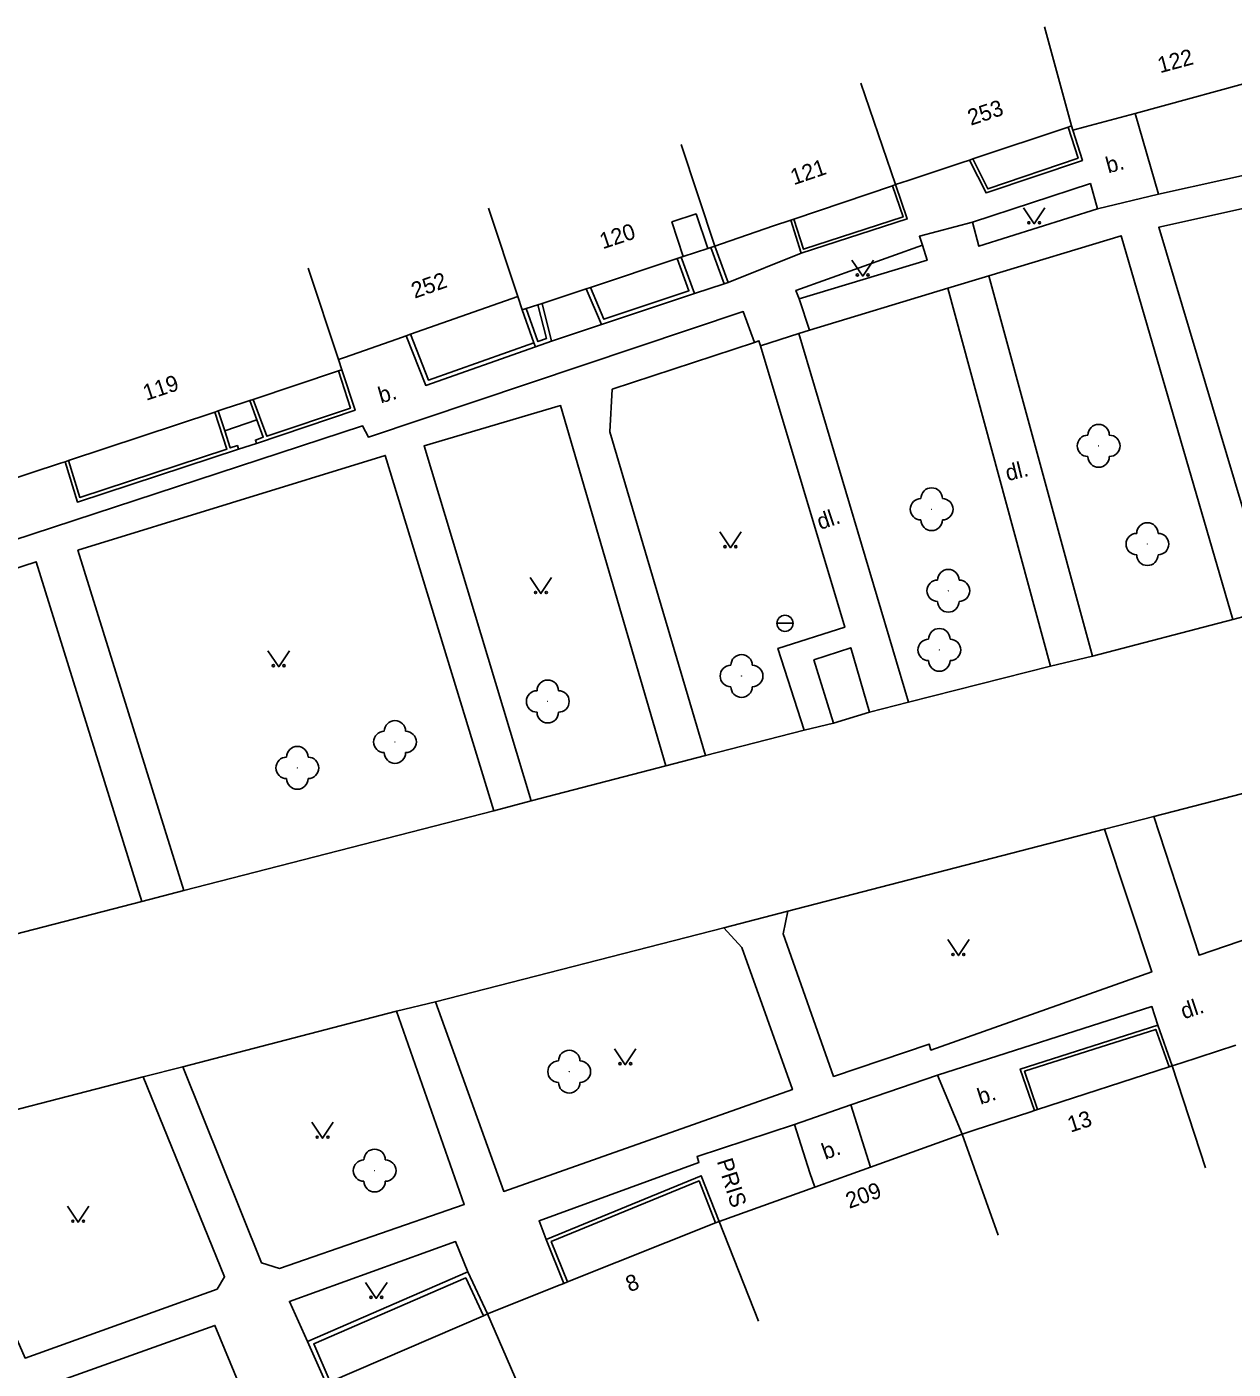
# Model space of a CAD drawing. Extents: x -577457 to -568404, y -1208466 to -1201387.
# Drawn here: x -574973.4 to -574917, y -1204035.2 to -1203972.5 of the extents above; entities that cross this region are included whole.
import ezdxf

# ---------------------------------------------------------------- set-up
doc = ezdxf.new("R2010")
doc.units = 0
for name, color, linetype in [('BUDOVY_MĚŘ', 7, 'Continuous'), ('POMOC_POPIS', 7, 'Continuous'), ('ROZHRANÍ_PLOCH', 7, 'Continuous'), ('ZELEŇ', 7, 'Continuous'), ('ZN_DOPLŇKOVÉ', 7, 'Continuous'), ('ZN_KULTUR', 7, 'Continuous'), ('Č_POPIS_ORIENT', 7, 'Continuous')]:
    doc.layers.add(name, color=color, linetype=linetype)

msp = doc.modelspace()

# ---------------------------------------------------------------- linework, layer by layer
at = {"layer": 'BUDOVY_MĚŘ'}
for points in [[(-574924.57, -1203977.14), (-574925.83, -1203972.51)], [(-574915.23, -1203974.82), (-574921.6, -1203976.55)], [(-574934.41, -1203975.14), (-574932.8, -1203979.88)], [(-574924.73, -1203977.19), (-574929.18, -1203978.68)], [(-574924.57, -1203977.14), (-574924.73, -1203977.19)], [(-574924.52, -1203977.34), (-574924.57, -1203977.14)], [(-574923.94, -1203977.18), (-574924.52, -1203977.34)], [(-574942.81, -1203978), (-574941.24, -1203982.75)], [(-574929.34, -1203978.73), (-574929.69, -1203978.85)], [(-574929.18, -1203978.68), (-574929.34, -1203978.73)], [(-574937.55, -1203981.49), (-574932.94, -1203979.93)], [(-574932.94, -1203979.93), (-574932.8, -1203979.88)], [(-574932.21, -1203979.68), (-574932.8, -1203979.88)], [(-574951.81, -1203980.98), (-574950.44, -1203985.11)], [(-574938.49, -1203981.81), (-574937.69, -1203981.54)], [(-574937.69, -1203981.54), (-574937.55, -1203981.49)], [(-574942.71, -1203983.24), (-574941.57, -1203982.86)], [(-574941.57, -1203982.86), (-574941.43, -1203982.81)], [(-574941.43, -1203982.81), (-574941.24, -1203982.75)], [(-574941.24, -1203982.75), (-574940.93, -1203982.64)], [(-574958.82, -1203988.05), (-574960.23, -1203983.78)], [(-574947.05, -1203984.68), (-574943, -1203983.33)], [(-574943, -1203983.33), (-574942.81, -1203983.27)], [(-574942.81, -1203983.27), (-574942.71, -1203983.24)], [(-574947.24, -1203984.74), (-574947.05, -1203984.68)], [(-574950.44, -1203985.11), (-574955.46, -1203986.87)], [(-574950.44, -1203985.11), (-574950.24, -1203985.73)], [(-574950.24, -1203985.73), (-574950.05, -1203985.67)], [(-574950.05, -1203985.67), (-574949.5, -1203985.49)], [(-574949.5, -1203985.49), (-574949.31, -1203985.43)], [(-574955.65, -1203986.94), (-574956.09, -1203987.09)], [(-574955.46, -1203986.87), (-574955.65, -1203986.94)], [(-574958.53, -1203987.95), (-574958.82, -1203988.05)], [(-574958.66, -1203988.53), (-574958.82, -1203988.05)], [(-574962.8, -1203989.91), (-574958.82, -1203988.58)], [(-574958.82, -1203988.58), (-574958.66, -1203988.53)], [(-574963.29, -1203990.07), (-574962.96, -1203989.96)], [(-574962.96, -1203989.96), (-574962.8, -1203989.91)], [(-574971.43, -1203992.77), (-574964.6, -1203990.5)], [(-574964.6, -1203990.5), (-574964.44, -1203990.45)], [(-574964.44, -1203990.45), (-574964.15, -1203990.35)], [(-574971.8, -1203992.89), (-574971.59, -1203992.82)], [(-574971.59, -1203992.82), (-574971.43, -1203992.77)], [(-574926.16, -1204023.08), (-574920.02, -1204021.09)], [(-574920.02, -1204021.09), (-574919.87, -1204021.04)], [(-574919.87, -1204021.04), (-574919.47, -1204020.91)], [(-574918.32, -1204025.8), (-574919.87, -1204021.04)], [(-574926.53, -1204023.2), (-574926.31, -1204023.13)], [(-574926.31, -1204023.13), (-574926.16, -1204023.08)], [(-574929.69, -1204024.23), (-574933.97, -1204025.77)], [(-574929.69, -1204024.23), (-574929.07, -1204024.03)], [(-574928, -1204028.94), (-574929.69, -1204024.23)], [(-574936.57, -1204026.7), (-574941.04, -1204028.31)], [(-574941.2, -1204028.37), (-574941.04, -1204028.31)], [(-574939.19, -1204032.96), (-574941.04, -1204028.31)], [(-574948.12, -1204031.13), (-574941.2, -1204028.37)], [(-574948.59, -1204031.32), (-574948.29, -1204031.2)], [(-574948.29, -1204031.2), (-574948.12, -1204031.13)], [(-574959.2, -1204035.79), (-574952.05, -1204032.71)], [(-574952.05, -1204032.71), (-574951.85, -1204032.62)], [(-574951.85, -1204032.62), (-574951.19, -1204032.36)], [(-574949.86, -1204037.21), (-574951.85, -1204032.62)]]:
    msp.add_lwpolyline(points, dxfattribs=at)
at = {"layer": 'ROZHRANÍ_PLOCH'}
for points in [[(-574921.6, -1203976.55), (-574920.52, -1203980.33)], [(-574920.52, -1203980.33), (-574914.31, -1203978.95)], [(-574929.2, -1203981.64), (-574923.69, -1203979.83), (-574923.36, -1203981.01)], [(-574923.36, -1203981.01), (-574920.52, -1203980.33)], [(-574915.17, -1203999.69), (-574920.5, -1203981.87), (-574912.77, -1203980.16), (-574908.46, -1203998.01)], [(-574923.36, -1203981.01), (-574928.91, -1203982.76), (-574929.2, -1203981.64)], [(-574931.53, -1203982.71), (-574931.68, -1203982.29), (-574929.2, -1203981.64)], [(-574928.44, -1203984.14), (-574922.25, -1203982.27), (-574917.04, -1204000.19)], [(-574940.61, -1203984.45), (-574937.2, -1203983.08)], [(-574937.3, -1203985.22), (-574937.45, -1203984.82), (-574931.53, -1203982.71)], [(-574931.53, -1203982.71), (-574931.32, -1203983.41), (-574937.3, -1203985.22)], [(-574930.36, -1203984.72), (-574928.44, -1203984.14)], [(-574928.44, -1203984.14), (-574923.6, -1204001.9)], [(-574936.82, -1203986.68), (-574930.36, -1203984.72)], [(-574925.55, -1204002.37), (-574930.36, -1203984.72)], [(-574936.82, -1203986.68), (-574937.3, -1203985.22)], [(-574995.99, -1204004.75), (-574996.24, -1204003.87), (-574973.96, -1203996.86), (-574974.07, -1203996.52), (-574957.69, -1203991.15), (-574957.42, -1203991.67), (-574939.91, -1203985.81), (-574939.38, -1203987.25)], [(-574948.86, -1203987.19), (-574946.53, -1203986.42)], [(-574939.11, -1203987.41), (-574937.31, -1203986.84)], [(-574937.31, -1203986.84), (-574936.82, -1203986.68)], [(-574932.19, -1204004.05), (-574937.31, -1203986.84)], [(-574941.67, -1204006.55), (-574946.14, -1203991.43), (-574946.03, -1203989.44), (-574939.38, -1203987.25)], [(-574939.11, -1203987.41), (-574939.18, -1203987.17), (-574939.38, -1203987.25)], [(-574937.06, -1204005.36), (-574938.29, -1204001.54), (-574935.17, -1204000.55), (-574939.11, -1203987.41)], [(-574949.81, -1204008.66), (-574954.82, -1203992.08), (-574948.44, -1203990.2), (-574943.53, -1204007.02)], [(-574964.13, -1203991.38), (-574962.63, -1203990.87)], [(-574963.49, -1203992.24), (-574962.65, -1203991.97)], [(-574966.04, -1204012.85), (-574970.99, -1203996.96), (-574956.63, -1203992.53), (-574951.56, -1204009.13)], [(-574982.66, -1204017.14), (-574987.79, -1204002.33), (-574972.94, -1203997.49), (-574968, -1204013.37)], [(-574917.04, -1204000.19), (-574915.17, -1203999.69)], [(-574923.6, -1204001.9), (-574917.04, -1204000.19)], [(-574935.7, -1204005.03), (-574936.61, -1204002.08), (-574934.89, -1204001.51), (-574934.01, -1204004.52)], [(-574925.55, -1204002.37), (-574923.6, -1204001.9)], [(-574932.19, -1204004.05), (-574925.55, -1204002.37)], [(-574935.7, -1204005.03), (-574934.01, -1204004.52)], [(-574934.01, -1204004.52), (-574932.19, -1204004.05)], [(-574937.06, -1204005.36), (-574935.7, -1204005.03)], [(-574941.67, -1204006.55), (-574937.06, -1204005.36)], [(-574949.81, -1204008.66), (-574943.53, -1204007.02)], [(-574943.53, -1204007.02), (-574941.67, -1204006.55)], [(-574920.73, -1204009.4), (-574918.62, -1204015.87), (-574911.78, -1204013.53), (-574913.34, -1204008.46), (-574914.29, -1204007.73)], [(-574920.73, -1204009.4), (-574914.29, -1204007.73)], [(-574951.56, -1204009.13), (-574949.81, -1204008.66)], [(-574966.04, -1204012.85), (-574951.56, -1204009.13)], [(-574923.03, -1204009.98), (-574920.73, -1204009.4)], [(-574937.82, -1204013.82), (-574938.04, -1204014.88), (-574935.69, -1204021.53), (-574931.23, -1204020.02), (-574931.14, -1204020.3), (-574920.83, -1204016.65), (-574923.03, -1204009.98)], [(-574937.82, -1204013.82), (-574923.03, -1204009.98)], [(-574968, -1204013.37), (-574966.04, -1204012.85)], [(-574982.66, -1204017.14), (-574968, -1204013.37)], [(-574940.82, -1204014.6), (-574937.82, -1204013.82)], [(-574954.29, -1204018.05), (-574951.1, -1204026.9), (-574937.61, -1204022.15), (-574939.98, -1204015.51), (-574940.82, -1204014.6)], [(-574954.29, -1204018.05), (-574940.82, -1204014.6)], [(-574956.11, -1204018.49), (-574954.29, -1204018.05)], [(-574930.84, -1204021.47), (-574920.82, -1204018.27), (-574920.54, -1204019.14)], [(-574966.09, -1204021.08), (-574956.11, -1204018.49)], [(-574966.09, -1204021.08), (-574962.41, -1204030.24), (-574961.58, -1204030.5), (-574952.94, -1204027.52), (-574956.11, -1204018.49)], [(-574967.94, -1204021.55), (-574966.09, -1204021.08)], [(-574978.06, -1204024.16), (-574967.94, -1204021.55)], [(-574978.06, -1204024.16), (-574973.46, -1204034.69), (-574964.49, -1204031.47), (-574964.14, -1204030.9), (-574967.94, -1204021.55)], [(-574934.89, -1204022.86), (-574930.84, -1204021.47)], [(-574930.84, -1204021.47), (-574929.69, -1204024.23)], [(-574937.51, -1204023.78), (-574934.89, -1204022.86)], [(-574933.97, -1204025.77), (-574934.89, -1204022.86)], [(-574949.11, -1204029.15), (-574949.45, -1204028.28), (-574941.98, -1204025.55), (-574942.07, -1204025.27), (-574937.51, -1204023.78)], [(-574937.51, -1204023.78), (-574936.8, -1204026.03), (-574936.57, -1204026.7)], [(-574960.26, -1204033.91), (-574961.11, -1204032.04), (-574953.35, -1204029.25), (-574952.77, -1204030.66)], [(-574970.41, -1204041.38), (-574972.83, -1204036.11), (-574964.59, -1204033.16), (-574963.43, -1204035.98)]]:
    msp.add_lwpolyline(points, dxfattribs=at)
at = {"layer": 'ZELEŇ'}
for centre in [(-574923.31, -1203992.08), (-574931.11, -1203995.04), (-574921.03, -1203996.67), (-574930.33, -1203998.85), (-574930.75, -1204001.61), (-574939.99, -1204002.83), (-574949.04, -1204004.02), (-574956.18, -1204005.91), (-574960.74, -1204007.12), (-574948.04, -1204021.31), (-574957.13, -1204025.93)]:
    msp.add_circle(centre, 0.0005, dxfattribs=at)
for centre, start, end in [((-574923.31, -1203991.58), 0, 179.99999), ((-574923.81, -1203992.08), 89.99999, 269.99999), ((-574922.81, -1203992.08), 270, 89.99999), ((-574923.31, -1203992.58), 179.99999, 359.99999), ((-574931.11, -1203994.54), 0, 179.99999), ((-574931.61, -1203995.04), 89.99999, 269.99999), ((-574930.61, -1203995.04), 270, 89.99999), ((-574931.11, -1203995.54), 179.99999, 359.99999), ((-574921.03, -1203996.17), 0, 179.99999), ((-574921.53, -1203996.67), 89.99999, 269.99999), ((-574920.53, -1203996.67), 270, 89.99999), ((-574921.03, -1203997.17), 179.99999, 359.99999), ((-574930.33, -1203998.35), 0, 179.99999), ((-574930.83, -1203998.85), 89.99999, 269.99999), ((-574929.83, -1203998.85), 270, 89.99999), ((-574930.33, -1203999.35), 179.99999, 359.99999), ((-574930.75, -1204001.11), 0, 179.99999), ((-574931.25, -1204001.61), 89.99999, 269.99999), ((-574930.25, -1204001.61), 270, 89.99999), ((-574939.99, -1204002.33), 0, 179.99999), ((-574940.49, -1204002.83), 89.99999, 269.99999), ((-574939.49, -1204002.83), 270, 89.99999), ((-574930.75, -1204002.11), 179.99999, 359.99999), ((-574949.04, -1204003.52), 0, 179.99999), ((-574949.54, -1204004.02), 89.99999, 269.99999), ((-574948.54, -1204004.02), 270, 89.99999), ((-574939.99, -1204003.33), 179.99999, 359.99999), ((-574949.04, -1204004.52), 179.99999, 359.99999), ((-574956.18, -1204005.41), 0, 179.99999), ((-574956.68, -1204005.91), 89.99999, 269.99999), ((-574955.68, -1204005.91), 270, 89.99999), ((-574960.74, -1204006.62), 0, 179.99999), ((-574956.18, -1204006.41), 179.99999, 359.99999), ((-574961.24, -1204007.12), 89.99999, 269.99999), ((-574960.24, -1204007.12), 270, 89.99999), ((-574960.74, -1204007.62), 179.99999, 359.99999), ((-574948.54, -1204021.31), 89.99999, 269.99999), ((-574948.04, -1204020.81), 0, 179.99999), ((-574947.54, -1204021.31), 270, 89.99999), ((-574948.04, -1204021.81), 179.99999, 359.99999), ((-574957.13, -1204025.43), 0, 179.99999), ((-574957.63, -1204025.93), 89.99999, 269.99999), ((-574956.63, -1204025.93), 270, 89.99999), ((-574957.13, -1204026.43), 179.99999, 359.99999)]:
    msp.add_arc(centre, 0.5, start, end, dxfattribs=at)
at = {"layer": 'ZN_DOPLŇKOVÉ'}
msp.add_line((-574938.335, -1204000.37), (-574937.585, -1204000.37), dxfattribs=at)
for points in [[(-574921.6, -1203976.55), (-574923.94, -1203977.18)], [(-574924.52, -1203977.34), (-574924.07, -1203978.75), (-574928.57, -1203980.27), (-574929.34, -1203978.73)], [(-574924.73, -1203977.19), (-574924.27, -1203978.64), (-574928.49, -1203980.08), (-574929.18, -1203978.68)], [(-574929.69, -1203978.85), (-574932.21, -1203979.68)], [(-574932.94, -1203979.93), (-574932.44, -1203981.39), (-574937.1, -1203982.9), (-574937.55, -1203981.49)], [(-574932.8, -1203979.88), (-574932.25, -1203981.48), (-574937.2, -1203983.08)], [(-574941.57, -1203982.86), (-574942.11, -1203981.25), (-574943.24, -1203981.62), (-574942.71, -1203983.24)], [(-574940.93, -1203982.64), (-574938.49, -1203981.81)], [(-574937.2, -1203983.08), (-574937.69, -1203981.54)], [(-574941.43, -1203982.81), (-574940.8, -1203984.52)], [(-574941.24, -1203982.75), (-574940.61, -1203984.45)], [(-574943, -1203983.33), (-574942.45, -1203984.84), (-574946.42, -1203986.17), (-574947.05, -1203984.68)], [(-574942.81, -1203983.27), (-574942.19, -1203984.97)], [(-574940.61, -1203984.45), (-574940.8, -1203984.52)], [(-574949.31, -1203985.43), (-574947.24, -1203984.74)], [(-574946.53, -1203986.42), (-574947.24, -1203984.74)], [(-574942.19, -1203984.97), (-574946.53, -1203986.42)], [(-574940.8, -1203984.52), (-574942.19, -1203984.97)], [(-574949.5, -1203985.49), (-574949.1, -1203987.06), (-574949.5, -1203987.21), (-574950.05, -1203985.67)], [(-574949.31, -1203985.43), (-574948.86, -1203987.19)], [(-574949.69, -1203987.27), (-574950.24, -1203985.73)], [(-574949.62, -1203987.46), (-574954.74, -1203989.26), (-574955.65, -1203986.94)], [(-574949.69, -1203987.27), (-574954.62, -1203989.01), (-574955.46, -1203986.87)], [(-574956.09, -1203987.09), (-574958.53, -1203987.95)], [(-574949.62, -1203987.46), (-574949.69, -1203987.27)], [(-574948.86, -1203987.19), (-574949.62, -1203987.46)], [(-574962.8, -1203989.91), (-574962.17, -1203991.63), (-574958.26, -1203990.32), (-574958.82, -1203988.58)], [(-574962.65, -1203991.97), (-574958.04, -1203990.42), (-574958.66, -1203988.53)], [(-574964.15, -1203990.35), (-574963.29, -1203990.07)], [(-574962.96, -1203989.96), (-574962.63, -1203990.87)], [(-574971.43, -1203992.77), (-574970.9, -1203994.49), (-574964.03, -1203992.24), (-574964.6, -1203990.5)], [(-574964.13, -1203991.38), (-574964.44, -1203990.45)], [(-574962.63, -1203990.87), (-574962.33, -1203991.68), (-574962.7, -1203991.81), (-574962.65, -1203991.97)], [(-574963.49, -1203992.24), (-574963.54, -1203992.07), (-574963.87, -1203992.18), (-574964.13, -1203991.38)], [(-574971.59, -1203992.82), (-574971.01, -1203994.71), (-574963.49, -1203992.24)], [(-574974.59, -1203993.81), (-574971.8, -1203992.89)], [(-574926.31, -1204023.13), (-574926.97, -1204021.19), (-574920.54, -1204019.14)], [(-574926.16, -1204023.08), (-574926.77, -1204021.29), (-574920.64, -1204019.34), (-574920.02, -1204021.09)], [(-574920.54, -1204019.14), (-574919.87, -1204021.04)], [(-574919.47, -1204020.91), (-574916.9, -1204020.08)], [(-574929.07, -1204024.03), (-574926.53, -1204023.2)], [(-574933.97, -1204025.77), (-574936.57, -1204026.7)], [(-574949.11, -1204029.15), (-574941.87, -1204026.17), (-574941.04, -1204028.31)], [(-574948.12, -1204031.13), (-574948.88, -1204029.25), (-574941.97, -1204026.41), (-574941.2, -1204028.37)], [(-574948.29, -1204031.2), (-574949.11, -1204029.15)], [(-574960.26, -1204033.91), (-574952.77, -1204030.66)], [(-574952.77, -1204030.66), (-574951.85, -1204032.62)], [(-574959.2, -1204035.79), (-574959.97, -1204034.02), (-574952.87, -1204030.94), (-574952.05, -1204032.71)], [(-574951.19, -1204032.36), (-574948.59, -1204031.32)], [(-574959.4, -1204035.88), (-574960.26, -1204033.91)]]:
    msp.add_lwpolyline(points, dxfattribs=at)
msp.add_circle((-574937.96, -1204000.37), 0.375, dxfattribs=at)
at = {"layer": 'ZN_KULTUR'}
for points in [[(-574926.82, -1203980.96), (-574926.32, -1203981.71), (-574925.82, -1203980.96)], [(-574934.83, -1203983.4), (-574934.33, -1203984.15), (-574933.83, -1203983.4)], [(-574941.01, -1203996.09), (-574940.51, -1203996.84), (-574940.01, -1203996.09)], [(-574949.86, -1203998.23), (-574949.36, -1203998.98), (-574948.86, -1203998.23)], [(-574962.11, -1204001.65), (-574961.61, -1204002.4), (-574961.11, -1204001.65)], [(-574930.36, -1204015.14), (-574929.86, -1204015.89), (-574929.36, -1204015.14)], [(-574945.92, -1204020.24), (-574945.42, -1204020.99), (-574944.92, -1204020.24)], [(-574960.06, -1204023.67), (-574959.56, -1204024.42), (-574959.06, -1204023.67)], [(-574971.48, -1204027.59), (-574970.98, -1204028.34), (-574970.48, -1204027.59)], [(-574957.55, -1204031.15), (-574957.05, -1204031.9), (-574956.55, -1204031.15)]]:
    msp.add_lwpolyline(points, dxfattribs=at)
for centre in [(-574926.57, -1203981.66), (-574926.07, -1203981.66), (-574934.58, -1203984.1), (-574934.08, -1203984.1), (-574940.76, -1203996.79), (-574940.26, -1203996.79), (-574949.61, -1203998.93), (-574949.11, -1203998.93), (-574961.86, -1204002.35), (-574961.36, -1204002.35), (-574930.11, -1204015.84), (-574929.61, -1204015.84), (-574945.67, -1204020.94), (-574945.17, -1204020.94), (-574959.81, -1204024.37), (-574959.31, -1204024.37), (-574971.23, -1204028.29), (-574970.73, -1204028.29), (-574957.3, -1204031.85), (-574956.8, -1204031.85)]:
    msp.add_circle(centre, 0.05, dxfattribs=at)

# ---------------------------------------------------------------- texts
at = {"layer": 'POMOC_POPIS'}
for s, rotation, p in [('b.', 15.14998, (-574922.86, -1203979.36)), ('b.', 15.96003, (-574956.84, -1203990.1)), ('dl.', 13.77001, (-574927.56, -1203993.73)), ('dl.', 18.44999, (-574936.32, -1203996.01)), ('dl.', 18.35997, (-574919.33, -1204018.87)), ('b.', 17.97999, (-574928.83, -1204022.86)), ('b.', 19.77999, (-574936.08, -1204025.43)), ('PRIS', 287.54002, (-574941.15, -1204025.49))]:
    msp.add_text(s, height=0.75, rotation=rotation, dxfattribs=at).set_placement(p)
at = {"layer": 'Č_POPIS_ORIENT'}
for s, rotation, p in [('122', 15.14998, (-574920.44, -1203974.68)), ('253', 18.38003, (-574929.28, -1203977.13)), ('121', 18.78998, (-574937.55, -1203979.91)), ('120', 18.31001, (-574946.47, -1203982.9)), ('252', 19.36998, (-574955.26, -1203985.21)), ('119', 18.33998, (-574967.8, -1203989.98)), ('13', 17.97999, (-574924.62, -1204024.16)), ('209', 19.77999, (-574934.96, -1204027.72)), ('8', 21.52001, (-574945.22, -1204031.62))]:
    msp.add_text(s, height=0.75, rotation=rotation, dxfattribs=at).set_placement(p)

doc.saveas('drawing.dxf')
